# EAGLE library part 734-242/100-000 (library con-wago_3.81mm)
Serie 734, Stiftleiste (für Leiterplatten) Einpressstift 0,6 x 0,6 mm / Series 734, Male header (for PCBs) Press-in pin 0.6 x 0.6 mm Polzahl / Pole No.: 12 Rastermaß / Pitch: 3.81 mm Bemessungsspannung / Rated Voltage: 160 V Nennstrom / Nominal Current: 8 A Farbe / Color: orange / orange Stand: 01.01.2012. Die jeweils aktuellen Daten zu diesem Artikel finden Sie in unserem Produktkatalog, den Sie unter www.wago.com einsehen können. As of: 01/01/2012. Please find the newest data for this article in our product catalogue, which can be viewed under www.wago.com.
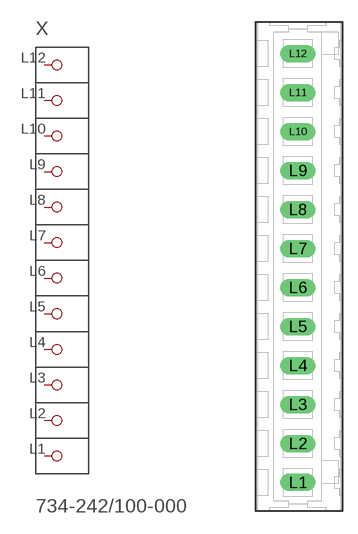
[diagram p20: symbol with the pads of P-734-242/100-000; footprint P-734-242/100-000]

Designator prefix X

## 734-242/100-000  [P-734-242/100-000]
L1  P1
L2  P2
L3  P3
L4  P4
L5  P5
L6  P6
L7  P7
L8  P8
L9  P9
L10  P10
L11  P11
L12  P12

## Footprint P-734-242/100-000 (pad centres in mm)
drill 1.15 long: L1 -0.1,-21.105; L2 -0.1,-17.295; L3 -0.1,-13.485; L4 -0.1,-9.675; L5 -0.1,-5.865; L6 -0.1,-2.055; L7 -0.1,1.755; L8 -0.1,5.565; L9 -0.1,9.375; L10 -0.1,13.185; L11 -0.1,16.995; L12 -0.1,20.805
